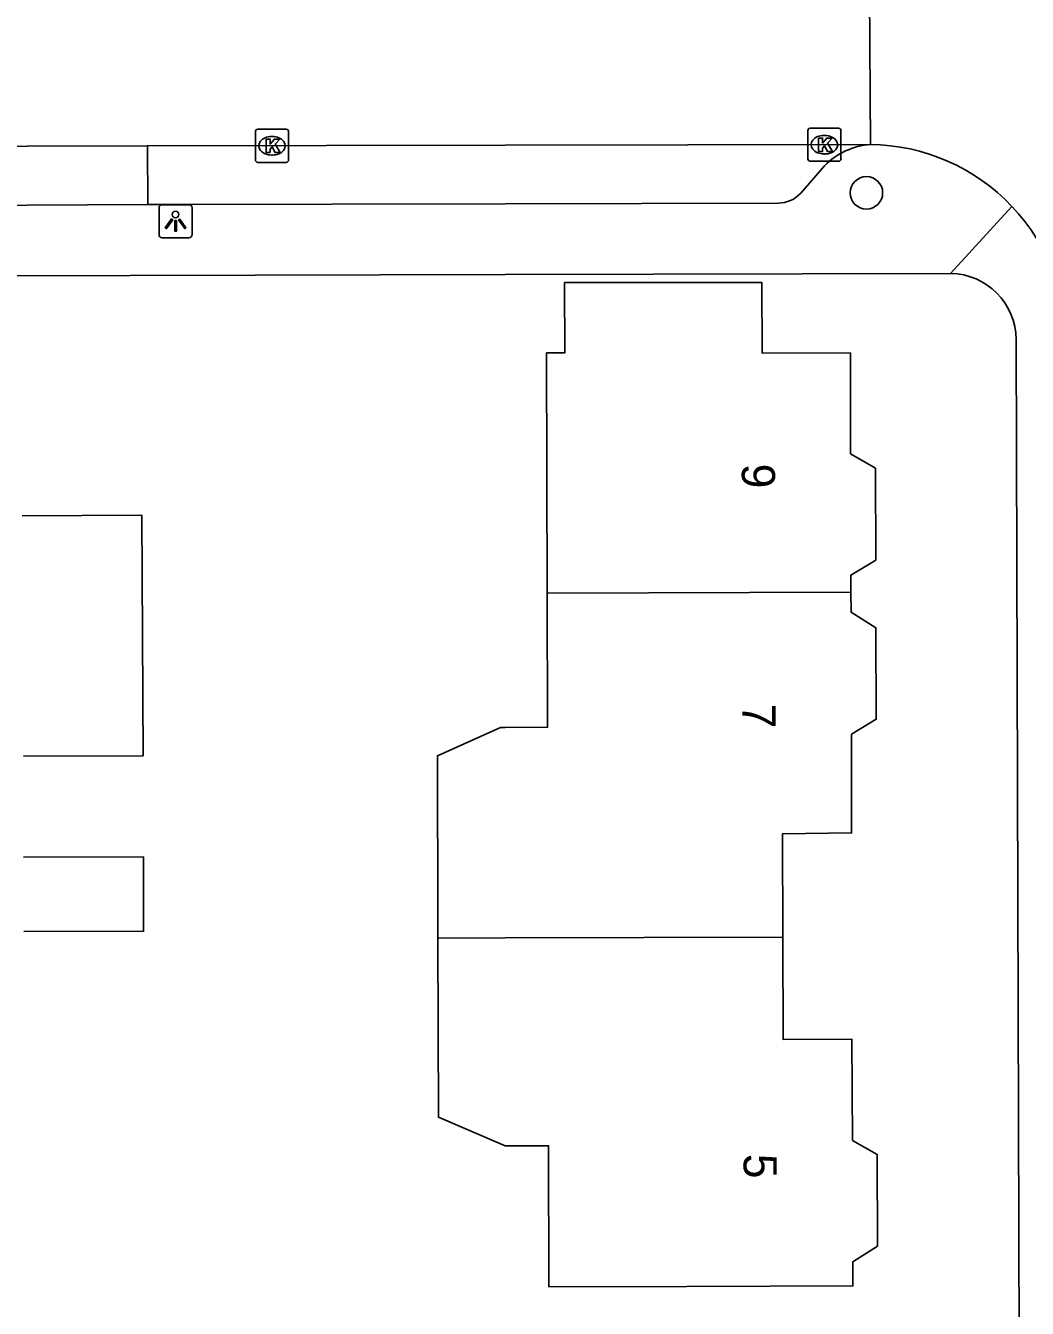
# Model space of a CAD drawing. Extents: x 160457 to 162082, y 388340 to 389736.
# Drawn here: x 160985.55 to 161015.74, y 388420.52 to 388459.2 of the extents above; entities that cross this region are included whole.
import ezdxf

# ---------------------------------------------------------------- set-up
doc = ezdxf.new("R2010")
doc.units = 0
for name, color, linetype in [('IMGEO_Boom', 7, 'Continuous'), ('IMGEO_Kolk', 7, 'Continuous'), ('IMGEO_Lichtpunt', 7, 'Continuous'), ('IMGEO_Muur', 7, 'Continuous'), ('IMGEO_Pand', 7, 'Continuous'), ('IMGEO_Pand_nummerreeks', 7, 'Continuous'), ('IMGEO_Parkeervlak_open', 7, 'Continuous'), ('IMGEO_Rijbaan_lokaal_open', 7, 'Continuous'), ('IMGEO_Voetpad_open', 7, 'Continuous')]:
    doc.layers.add(name, color=color, linetype=linetype)

msp = doc.modelspace()

# ---------------------------------------------------------------- linework, layer by layer
at = {"layer": 'IMGEO_Boom'}
msp.add_circle((161010.892, 388454.161), 0.489, dxfattribs=at)
at = {"layer": 'IMGEO_Kolk'}
for p, q in [((160992.476, 388455.155), (160992.476, 388456.007)), ((160992.551, 388456.081), (160993.403, 388456.081)), ((160992.964, 388455.861), (160992.989, 388455.861)), ((160993.477, 388456.007), (160993.477, 388455.155)), ((161009.124, 388455.187), (161009.124, 388456.039)), ((161009.199, 388456.113), (161010.051, 388456.113)), ((161009.612, 388455.893), (161009.637, 388455.893)), ((161010.125, 388456.039), (161010.125, 388455.187)), ((160993.403, 388455.081), (160992.551, 388455.081)), ((160992.987, 388455.301), (160992.962, 388455.301)), ((161010.051, 388455.113), (161009.199, 388455.113)), ((161009.635, 388455.333), (161009.61, 388455.333))]:
    msp.add_line(p, q, dxfattribs=at)
for points in [[(160992.476, 388455.155), (160992.476, 388456.007)], [(160992.551, 388456.081), (160993.403, 388456.081)], [(160992.797, 388455.781), (160992.92, 388455.781), (160992.92, 388455.63), (160993.05, 388455.781), (160993.214, 388455.781), (160993.068, 388455.63), (160993.221, 388455.381), (160993.069, 388455.381), (160992.984, 388455.545), (160992.92, 388455.478), (160992.92, 388455.381), (160992.797, 388455.381), (160992.797, 388455.781)], [(160993.477, 388456.007), (160993.477, 388455.155)], [(161009.124, 388455.187), (161009.124, 388456.039)], [(161009.199, 388456.113), (161010.051, 388456.113)], [(161009.445, 388455.813), (161009.568, 388455.813), (161009.568, 388455.662), (161009.698, 388455.813), (161009.862, 388455.813), (161009.716, 388455.662), (161009.869, 388455.413), (161009.717, 388455.413), (161009.632, 388455.577), (161009.568, 388455.51), (161009.568, 388455.413), (161009.445, 388455.413), (161009.445, 388455.813)], [(161010.125, 388456.039), (161010.125, 388455.187)], [(160993.403, 388455.081), (160992.551, 388455.081)], [(161010.051, 388455.113), (161009.199, 388455.113)]]:
    msp.add_lwpolyline(points, dxfattribs=at)
for centre, start, end in [((160992.553, 388456.005), 91.552, 178.448), ((160992.553, 388456.005), 91.552, 178.448), ((160993.401, 388456.005), 1.552, 88.448), ((160993.401, 388456.005), 1.552, 88.448), ((161009.201, 388456.037), 91.552, 178.448), ((161009.201, 388456.037), 91.552, 178.448), ((161010.049, 388456.037), 1.552, 88.448), ((161010.049, 388456.037), 1.552, 88.448), ((160992.553, 388455.157), 181.552, 268.448), ((160992.553, 388455.157), 181.552, 268.448), ((160993.401, 388455.157), 271.552, 358.448), ((160993.401, 388455.157), 271.552, 358.448), ((161009.201, 388455.189), 181.552, 268.448), ((161009.201, 388455.189), 181.552, 268.448), ((161010.049, 388455.189), 271.552, 358.448), ((161010.049, 388455.189), 271.552, 358.448)]:
    msp.add_arc(centre, 0.0765, start, end, dxfattribs=at)
for centre, major_axis, ratio, start_param, end_param in [((160992.963, 388455.581), (-0.387, 0.002), 0.722429, 4.712389, 7.853982), ((160992.988, 388455.581), (-0.39, 0.002), 0.717154, 1.570796, 4.712389), ((161009.611, 388455.613), (-0.387, 0.002), 0.722429, 4.712389, 7.853982), ((161009.636, 388455.613), (-0.39, 0.002), 0.717154, 1.570796, 4.712389)]:
    msp.add_ellipse(centre, major_axis=major_axis, ratio=ratio, start_param=start_param, end_param=end_param, dxfattribs=at)
at = {"layer": 'IMGEO_Lichtpunt'}
for p, q in [((160990.475, 388453.805), (160989.667, 388453.805)), ((160990.475, 388453.805), (160989.667, 388453.805)), ((160989.573, 388453.71), (160989.573, 388452.903)), ((160989.573, 388453.71), (160989.573, 388452.903)), ((160990.569, 388452.903), (160990.569, 388453.71)), ((160990.569, 388452.903), (160990.569, 388453.71)), ((160989.667, 388452.809), (160990.475, 388452.809)), ((160989.667, 388452.809), (160990.475, 388452.809))]:
    msp.add_line(p, q, dxfattribs=at)
for points in [[(160989.947, 388453.374), (160989.986, 388453.346), (160989.798, 388453.084), (160989.76, 388453.111), (160989.947, 388453.374)], [(160990.049, 388453.326), (160990.096, 388453.326), (160990.096, 388453.004), (160990.049, 388453.004), (160990.049, 388453.326)], [(160990.159, 388453.346), (160990.197, 388453.373), (160990.384, 388453.111), (160990.345, 388453.083), (160990.159, 388453.346)]]:
    msp.add_lwpolyline(points, dxfattribs=at)
msp.add_circle((160990.072, 388453.508), 0.0994, dxfattribs=at)
for centre, start, end in [((160989.667, 388453.71), 90, 180), ((160989.667, 388453.71), 90, 180), ((160990.475, 388453.71), 0, 90), ((160990.475, 388453.71), 0, 90), ((160989.667, 388452.903), 180, 270), ((160989.667, 388452.903), 180, 270), ((160990.475, 388452.903), 270, 0), ((160990.475, 388452.903), 270, 360)]:
    msp.add_arc(centre, 0.0946, start, end, dxfattribs=at)
at = {"layer": 'IMGEO_Muur'}
msp.add_lwpolyline([(161000, 388451.701), (160988.705, 388451.673)], dxfattribs=at)
at = {"layer": 'IMGEO_Pand'}
for points in [[(161001.27, 388442.093), (161001.251, 388449.334), (161001.801, 388449.336), (161001.796, 388451.456), (161007.744, 388451.458), (161007.749, 388449.329), (161010.408, 388449.335), (161010.416, 388446.296), (161011.167, 388445.858), (161011.174, 388443.088), (161010.425, 388442.636), (161010.426, 388442.118)], [(160985.449, 388444.423), (160989.049, 388444.445), (160989.093, 388437.186), (160985.483, 388437.176)], [(160997.978, 388431.687), (160997.977, 388432.187), (160997.964, 388437.186), (160999.862, 388438.041), (161000, 388438.041), (161001.281, 388438.044), (161001.27, 388442.093)], [(161010.426, 388442.118), (161001.27, 388442.093)], [(161010.426, 388442.118), (161010.428, 388441.516), (161011.18, 388441.048), (161011.187, 388438.288), (161010.437, 388437.836), (161010.445, 388434.86), (161008.358, 388434.831), (161008.368, 388431.715)], [(160985.489, 388434.128), (160989.101, 388434.135), (160989.105, 388431.895), (160985.493, 388431.888)], [(161008.368, 388431.715), (161008.378, 388428.633), (161010.456, 388428.637), (161010.467, 388425.588), (161011.219, 388425.161), (161011.229, 388422.401), (161010.48, 388421.927), (161010.483, 388421.197), (161005.484, 388421.184), (161001.324, 388421.173), (161001.313, 388425.423), (161000, 388425.42), (160997.992, 388426.285), (160997.978, 388431.687)], [(161008.368, 388431.715), (161000, 388431.693), (160997.978, 388431.687)]]:
    msp.add_lwpolyline(points, dxfattribs=at)
at = {"layer": 'IMGEO_Parkeervlak_open'}
msp.add_lwpolyline([(160989.227, 388455.575), (160989.23, 388453.807)], dxfattribs=at)
at = {"layer": 'IMGEO_Rijbaan_lokaal_open'}
for points in [[(161010.987, 388460.172), (161011.014, 388455.617)], [(160981.957, 388455.561), (160989.227, 388455.575)], [(161011.014, 388455.617), (161000, 388455.596), (160989.227, 388455.575)]]:
    msp.add_lwpolyline(points, dxfattribs=at)
for centre, radius, start, end in [((161010.951, 388449.667), 5.951, 43.37, 89.3952), ((161010.952, 388449.664), 5.952, 357.3941, 43.3951)]:
    msp.add_arc(centre, radius, start, end, dxfattribs=at)
at = {"layer": 'IMGEO_Voetpad_open'}
for points in [[(161008.915, 388454.157), (161009.626, 388454.976)], [(160981.961, 388453.773), (160989.23, 388453.807)], [(160989.23, 388453.807), (160989.545, 388453.808), (161000, 388453.833), (161008.233, 388453.852)], [(161015.277, 388453.753), (161013.43, 388451.734)], [(161013.43, 388451.734), (161000, 388451.701), (160988.705, 388451.673), (160892.347, 388451.433)], [(161010.95, 388390.757), (161015.566, 388395.957), (161015.408, 388449.738)]]:
    msp.add_lwpolyline(points, dxfattribs=at)
for centre, radius, start, end in [((161011.157, 388453.485), 2.137, 93.8291, 135.7474), ((161008.237, 388454.758), 0.906, 269.7522, 318.4376), ((161013.384, 388449.71), 2.024, 0.7801, 88.7009)]:
    msp.add_arc(centre, radius, start, end, dxfattribs=at)

# ---------------------------------------------------------------- texts
at = {"layer": 'IMGEO_Pand_nummerreeks'}
for s, rotation, p in [('9', 270.146, (161007.136, 388445.993)), ('7', 270.1469, (161007.155, 388438.756)), ('5', 270.2079, (161007.189, 388425.18))]:
    msp.add_text(s, height=1, rotation=rotation, dxfattribs=at).set_placement(p)

doc.saveas('drawing.dxf')
